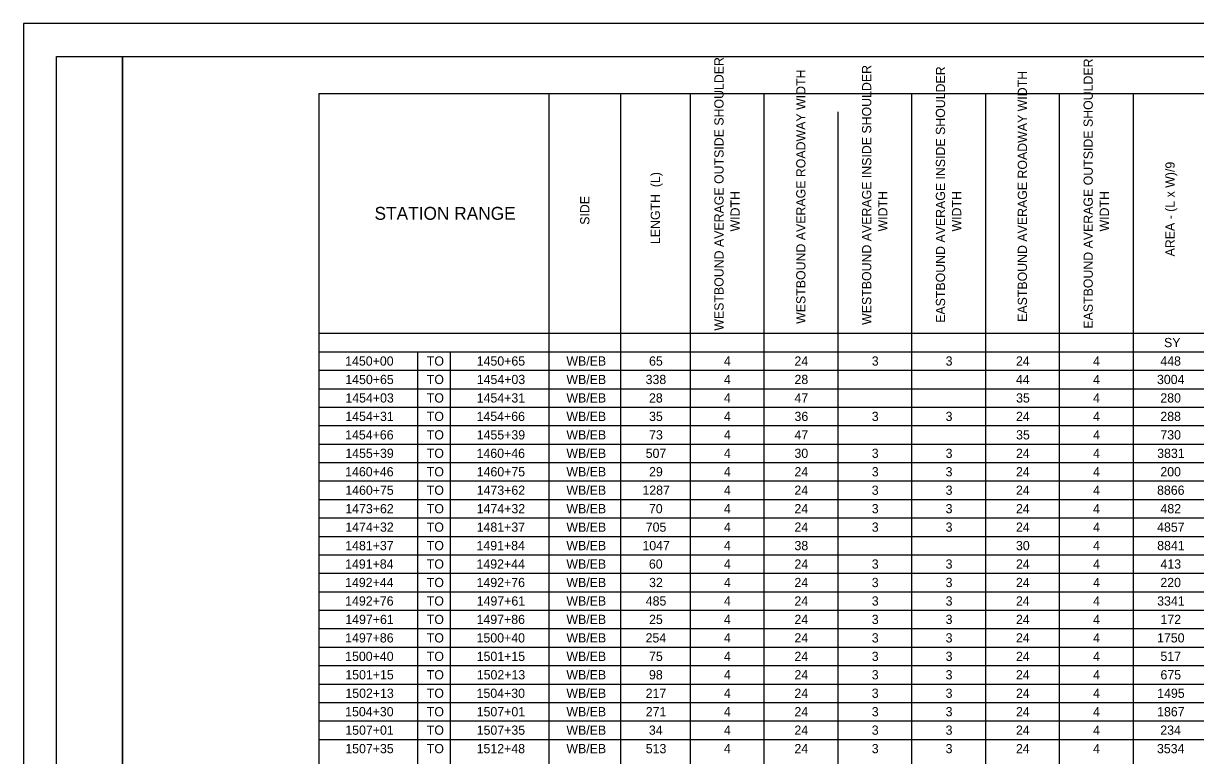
# Model space of a CAD drawing. Extents: x 0 to 34, y 0 to 22.
# Drawn here: x 0 to 17.78, y 10.89 to 22 of the extents above; entities that cross this region are included whole.
import ezdxf

# ---------------------------------------------------------------- set-up
doc = ezdxf.new("R2010")
doc.units = 0
for name, color, linetype in [('SH_Border', 7, 'Continuous'), ('SH_Cut_Line', 7, 'Continuous'), ('SH_Data', 7, 'Continuous'), ('SH_Text', 7, 'Continuous')]:
    doc.layers.add(name, color=color, linetype=linetype)

msp = doc.modelspace()

# ---------------------------------------------------------------- linework, layer by layer
at = {"layer": 'SH_Border'}
for points in [[(0.5, 21.5), (1.5, 21.5), (1.5, 0.5), (0.5, 0.5)], [(1.5, 21.5), (33.5, 21.5), (33.5, 0.5), (1.5, 0.5)]]:
    msp.add_lwpolyline(points, close=True, dxfattribs=at)
at = {"layer": 'SH_Cut_Line'}
msp.add_lwpolyline([(0, 0), (34, 0), (34, 22), (0, 22)], close=True, dxfattribs=at)
at = {"layer": 'SH_Data'}
for p, q in [((4.478, 20.939), (29.151, 20.939)), ((4.478, 20.939), (4.478, 1.339)), ((7.97, 20.939), (7.97, 1.899)), ((9.057, 20.939), (9.057, 1.899)), ((10.111, 20.939), (10.111, 1.899)), ((11.231, 20.939), (11.231, 1.899)), ((13.471, 20.939), (13.471, 1.339)), ((14.591, 20.939), (14.591, 1.339)), ((15.711, 20.939), (15.711, 1.339)), ((16.831, 20.939), (16.831, 1.339)), ((12.351, 20.659), (12.351, 1.899)), ((4.478, 17.299), (29.151, 17.299)), ((4.478, 17.019), (25.791, 17.019)), ((5.977, 17.019), (5.977, 1.899)), ((6.471, 17.019), (6.471, 1.899)), ((4.478, 16.739), (23.551, 16.739)), ((4.478, 16.459), (23.551, 16.459)), ((4.478, 16.179), (23.551, 16.179)), ((4.478, 15.899), (23.551, 15.899)), ((4.478, 15.619), (23.551, 15.619)), ((4.478, 15.339), (23.551, 15.339)), ((4.478, 15.059), (23.551, 15.059)), ((4.478, 14.779), (23.551, 14.779)), ((4.478, 14.499), (23.551, 14.499)), ((4.478, 14.219), (23.551, 14.219)), ((4.478, 13.939), (23.551, 13.939)), ((4.478, 13.659), (23.551, 13.659)), ((4.478, 13.379), (23.551, 13.379)), ((4.478, 13.099), (23.551, 13.099)), ((4.478, 12.819), (23.551, 12.819)), ((4.478, 12.539), (23.551, 12.539)), ((4.478, 12.259), (23.551, 12.259)), ((4.478, 11.979), (23.551, 11.979)), ((4.478, 11.699), (23.551, 11.699)), ((4.478, 11.419), (23.551, 11.419)), ((4.478, 11.139), (23.551, 11.139))]:
    msp.add_line(p, q, dxfattribs=at)

# ---------------------------------------------------------------- texts
at = {"layer": 'SH_Text'}
for s, p in [('WESTBOUND AVERAGE OUTSIDE SHOULDER ', (10.619, 17.339)), ('WESTBOUND AVERAGE INSIDE SHOULDER ', (12.859, 17.427)), ('EASTBOUND AVERAGE INSIDE SHOULDER ', (13.979, 17.458)), ('EASTBOUND AVERAGE OUTSIDE SHOULDER ', (16.219, 17.37)), ('WESTBOUND AVERAGE ROADWAY WIDTH', (11.861, 17.442)), ('EASTBOUND AVERAGE ROADWAY WIDTH', (15.221, 17.473)), ('AREA - (L x W)/9', (17.461, 18.466)), ('LENGTH  (L)', (9.654, 18.653)), ('WIDTH', (10.864, 18.844)), ('WIDTH', (13.104, 18.844)), ('WIDTH', (14.224, 18.844)), ('WIDTH', (16.464, 18.844)), ('SIDE', (8.584, 18.945))]:
    msp.add_text(s, height=0.14, rotation=90, dxfattribs=at).set_placement(p)
for s, height, p in [('STATION RANGE', 0.196, (5.325, 19.021)), ('SY', 0.14, (17.3, 17.089)), ('1450+00', 0.14, (4.88, 16.809)), ('TO', 0.14, (6.118, 16.809)), ('1450+65', 0.14, (6.875, 16.809)), ('WB/EB', 0.14, (8.235, 16.809)), ('65', 0.14, (9.489, 16.809)), ('4', 0.14, (10.624, 16.809)), ('24', 0.14, (11.694, 16.809)), ('3', 0.14, (12.867, 16.809)), ('3', 0.14, (13.987, 16.809)), ('24', 0.14, (15.054, 16.809)), ('4', 0.14, (16.224, 16.809)), ('448', 0.14, (17.244, 16.809)), ('1450+65', 0.14, (4.882, 16.529)), ('TO', 0.14, (6.118, 16.529)), ('1454+03', 0.14, (6.876, 16.529)), ('WB/EB', 0.14, (8.235, 16.529)), ('338', 0.14, (9.437, 16.529)), ('4', 0.14, (10.624, 16.529)), ('28', 0.14, (11.695, 16.529)), ('44', 0.14, (15.054, 16.529)), ('4', 0.14, (16.224, 16.529)), ('3004', 0.14, (17.193, 16.529)), ('1454+03', 0.14, (4.883, 16.249)), ('TO', 0.14, (6.118, 16.249)), ('1454+31', 0.14, (6.875, 16.249)), ('WB/EB', 0.14, (8.235, 16.249)), ('28', 0.14, (9.488, 16.249)), ('4', 0.14, (10.624, 16.249)), ('47', 0.14, (11.695, 16.249)), ('35', 0.14, (15.056, 16.249)), ('4', 0.14, (16.224, 16.249)), ('280', 0.14, (17.244, 16.249)), ('1454+31', 0.14, (4.882, 15.969)), ('TO', 0.14, (6.118, 15.969)), ('1454+66', 0.14, (6.873, 15.969)), ('WB/EB', 0.14, (8.235, 15.969)), ('35', 0.14, (9.489, 15.969)), ('4', 0.14, (10.624, 15.969)), ('36', 0.14, (11.695, 15.969)), ('3', 0.14, (12.867, 15.969)), ('3', 0.14, (13.987, 15.969)), ('24', 0.14, (15.054, 15.969)), ('4', 0.14, (16.224, 15.969)), ('288', 0.14, (17.244, 15.969)), ('1454+66', 0.14, (4.88, 15.689)), ('TO', 0.14, (6.118, 15.689)), ('1455+39', 0.14, (6.875, 15.689)), ('WB/EB', 0.14, (8.235, 15.689)), ('73', 0.14, (9.49, 15.689)), ('4', 0.14, (10.624, 15.689)), ('47', 0.14, (11.695, 15.689)), ('35', 0.14, (15.056, 15.689)), ('4', 0.14, (16.224, 15.689)), ('730', 0.14, (17.244, 15.689)), ('1455+39', 0.14, (4.882, 15.409)), ('TO', 0.14, (6.118, 15.409)), ('1460+46', 0.14, (6.873, 15.409)), ('WB/EB', 0.14, (8.235, 15.409)), ('507', 0.14, (9.438, 15.409)), ('4', 0.14, (10.624, 15.409)), ('30', 0.14, (11.694, 15.409)), ('3', 0.14, (12.867, 15.409)), ('3', 0.14, (13.987, 15.409)), ('24', 0.14, (15.054, 15.409)), ('4', 0.14, (16.224, 15.409)), ('3831', 0.14, (17.196, 15.409)), ('1460+46', 0.14, (4.88, 15.129)), ('TO', 0.14, (6.118, 15.129)), ('1460+75', 0.14, (6.875, 15.129)), ('WB/EB', 0.14, (8.235, 15.129)), ('29', 0.14, (9.489, 15.129)), ('4', 0.14, (10.624, 15.129)), ('24', 0.14, (11.694, 15.129)), ('3', 0.14, (12.867, 15.129)), ('3', 0.14, (13.987, 15.129)), ('24', 0.14, (15.054, 15.129)), ('4', 0.14, (16.224, 15.129)), ('200', 0.14, (17.244, 15.129)), ('1460+75', 0.14, (4.882, 14.849)), ('TO', 0.14, (6.118, 14.849)), ('1473+62', 0.14, (6.875, 14.849)), ('WB/EB', 0.14, (8.235, 14.849)), ('1287', 0.14, (9.388, 14.849)), ('4', 0.14, (10.624, 14.849)), ('24', 0.14, (11.694, 14.849)), ('3', 0.14, (12.867, 14.849)), ('3', 0.14, (13.987, 14.849)), ('24', 0.14, (15.054, 14.849)), ('4', 0.14, (16.224, 14.849)), ('8866', 0.14, (17.194, 14.849)), ('1473+62', 0.14, (4.882, 14.569)), ('TO', 0.14, (6.118, 14.569)), ('1474+32', 0.14, (6.875, 14.569)), ('WB/EB', 0.14, (8.235, 14.569)), ('70', 0.14, (9.487, 14.569)), ('4', 0.14, (10.624, 14.569)), ('24', 0.14, (11.694, 14.569)), ('3', 0.14, (12.867, 14.569)), ('3', 0.14, (13.987, 14.569)), ('24', 0.14, (15.054, 14.569)), ('4', 0.14, (16.224, 14.569)), ('482', 0.14, (17.246, 14.569)), ('1474+32', 0.14, (4.882, 14.289)), ('TO', 0.14, (6.118, 14.289)), ('1481+37', 0.14, (6.874, 14.289)), ('WB/EB', 0.14, (8.235, 14.289)), ('705', 0.14, (9.439, 14.289)), ('4', 0.14, (10.624, 14.289)), ('24', 0.14, (11.694, 14.289)), ('3', 0.14, (12.867, 14.289)), ('3', 0.14, (13.987, 14.289)), ('24', 0.14, (15.054, 14.289)), ('4', 0.14, (16.224, 14.289)), ('4857', 0.14, (17.195, 14.289)), ('1481+37', 0.14, (4.881, 14.009)), ('TO', 0.14, (6.118, 14.009)), ('1491+84', 0.14, (6.872, 14.009)), ('WB/EB', 0.14, (8.235, 14.009)), ('1047', 0.14, (9.388, 14.009)), ('4', 0.14, (10.624, 14.009)), ('38', 0.14, (11.695, 14.009)), ('30', 0.14, (15.054, 14.009)), ('4', 0.14, (16.224, 14.009)), ('8841', 0.14, (17.196, 14.009)), ('1491+84', 0.14, (4.879, 13.729)), ('TO', 0.14, (6.118, 13.729)), ('1492+44', 0.14, (6.872, 13.729)), ('WB/EB', 0.14, (8.235, 13.729)), ('60', 0.14, (9.487, 13.729)), ('4', 0.14, (10.624, 13.729)), ('24', 0.14, (11.694, 13.729)), ('3', 0.14, (12.867, 13.729)), ('3', 0.14, (13.987, 13.729)), ('24', 0.14, (15.054, 13.729)), ('4', 0.14, (16.224, 13.729)), ('413', 0.14, (17.246, 13.729)), ('1492+44', 0.14, (4.879, 13.449)), ('TO', 0.14, (6.118, 13.449)), ('1492+76', 0.14, (6.873, 13.449)), ('WB/EB', 0.14, (8.235, 13.449)), ('32', 0.14, (9.489, 13.449)), ('4', 0.14, (10.624, 13.449)), ('24', 0.14, (11.694, 13.449)), ('3', 0.14, (12.867, 13.449)), ('3', 0.14, (13.987, 13.449)), ('24', 0.14, (15.054, 13.449)), ('4', 0.14, (16.224, 13.449)), ('220', 0.14, (17.244, 13.449)), ('1492+76', 0.14, (4.88, 13.169)), ('TO', 0.14, (6.118, 13.169)), ('1497+61', 0.14, (6.875, 13.169)), ('WB/EB', 0.14, (8.235, 13.169)), ('485', 0.14, (9.439, 13.169)), ('4', 0.14, (10.624, 13.169)), ('24', 0.14, (11.694, 13.169)), ('3', 0.14, (12.867, 13.169)), ('3', 0.14, (13.987, 13.169)), ('24', 0.14, (15.054, 13.169)), ('4', 0.14, (16.224, 13.169)), ('3341', 0.14, (17.196, 13.169)), ('1497+61', 0.14, (4.882, 12.889)), ('TO', 0.14, (6.118, 12.889)), ('1497+86', 0.14, (6.873, 12.889)), ('WB/EB', 0.14, (8.235, 12.889)), ('25', 0.14, (9.489, 12.889)), ('4', 0.14, (10.624, 12.889)), ('24', 0.14, (11.694, 12.889)), ('3', 0.14, (12.867, 12.889)), ('3', 0.14, (13.987, 12.889)), ('24', 0.14, (15.054, 12.889)), ('4', 0.14, (16.224, 12.889)), ('172', 0.14, (17.246, 12.889)), ('1497+86', 0.14, (4.88, 12.609)), ('TO', 0.14, (6.118, 12.609)), ('1500+40', 0.14, (6.873, 12.609)), ('WB/EB', 0.14, (8.235, 12.609)), ('254', 0.14, (9.436, 12.609)), ('4', 0.14, (10.624, 12.609)), ('24', 0.14, (11.694, 12.609)), ('3', 0.14, (12.867, 12.609)), ('3', 0.14, (13.987, 12.609)), ('24', 0.14, (15.054, 12.609)), ('4', 0.14, (16.224, 12.609)), ('1750', 0.14, (17.194, 12.609)), ('1500+40', 0.14, (4.88, 12.329)), ('TO', 0.14, (6.118, 12.329)), ('1501+15', 0.14, (6.875, 12.329)), ('WB/EB', 0.14, (8.235, 12.329)), ('75', 0.14, (9.489, 12.329)), ('4', 0.14, (10.624, 12.329)), ('24', 0.14, (11.694, 12.329)), ('3', 0.14, (12.867, 12.329)), ('3', 0.14, (13.987, 12.329)), ('24', 0.14, (15.054, 12.329)), ('4', 0.14, (16.224, 12.329)), ('517', 0.14, (17.245, 12.329)), ('1501+15', 0.14, (4.882, 12.049)), ('TO', 0.14, (6.118, 12.049)), ('1502+13', 0.14, (6.876, 12.049)), ('WB/EB', 0.14, (8.235, 12.049)), ('98', 0.14, (9.488, 12.049)), ('4', 0.14, (10.624, 12.049)), ('24', 0.14, (11.694, 12.049)), ('3', 0.14, (12.867, 12.049)), ('3', 0.14, (13.987, 12.049)), ('24', 0.14, (15.054, 12.049)), ('4', 0.14, (16.224, 12.049)), ('675', 0.14, (17.246, 12.049)), ('1502+13', 0.14, (4.883, 11.769)), ('TO', 0.14, (6.118, 11.769)), ('1504+30', 0.14, (6.873, 11.769)), ('WB/EB', 0.14, (8.235, 11.769)), ('217', 0.14, (9.438, 11.769)), ('24', 0.14, (11.694, 11.769)), ('3', 0.14, (12.867, 11.769)), ('3', 0.14, (13.987, 11.769)), ('24', 0.14, (15.054, 11.769)), ('1495', 0.14, (17.196, 11.769)), ('4', 0.14, (10.624, 11.769)), ('4', 0.14, (16.224, 11.769)), ('1504+30', 0.14, (4.88, 11.489)), ('TO', 0.14, (6.118, 11.489)), ('1507+01', 0.14, (6.875, 11.489)), ('WB/EB', 0.14, (8.235, 11.489)), ('271', 0.14, (9.439, 11.489)), ('4', 0.14, (10.624, 11.489)), ('24', 0.14, (11.694, 11.489)), ('3', 0.14, (12.867, 11.489)), ('3', 0.14, (13.987, 11.489)), ('24', 0.14, (15.054, 11.489)), ('4', 0.14, (16.224, 11.489)), ('1867', 0.14, (17.195, 11.489)), ('1507+01', 0.14, (4.882, 11.209)), ('TO', 0.14, (6.118, 11.209)), ('1507+35', 0.14, (6.875, 11.209)), ('WB/EB', 0.14, (8.235, 11.209)), ('34', 0.14, (9.486, 11.209)), ('4', 0.14, (10.624, 11.209)), ('24', 0.14, (11.694, 11.209)), ('3', 0.14, (12.867, 11.209)), ('3', 0.14, (13.987, 11.209)), ('24', 0.14, (15.054, 11.209)), ('4', 0.14, (16.224, 11.209)), ('234', 0.14, (17.243, 11.209)), ('1507+35', 0.14, (4.882, 10.929)), ('TO', 0.14, (6.118, 10.929)), ('1512+48', 0.14, (6.874, 10.929)), ('WB/EB', 0.14, (8.235, 10.929)), ('513', 0.14, (9.439, 10.929)), ('4', 0.14, (10.624, 10.929)), ('24', 0.14, (11.694, 10.929)), ('3', 0.14, (12.867, 10.929)), ('3', 0.14, (13.987, 10.929)), ('24', 0.14, (15.054, 10.929)), ('4', 0.14, (16.224, 10.929)), ('3534', 0.14, (17.193, 10.929))]:
    msp.add_text(s, height=height, dxfattribs=at).set_placement(p)

doc.saveas('drawing.dxf')
